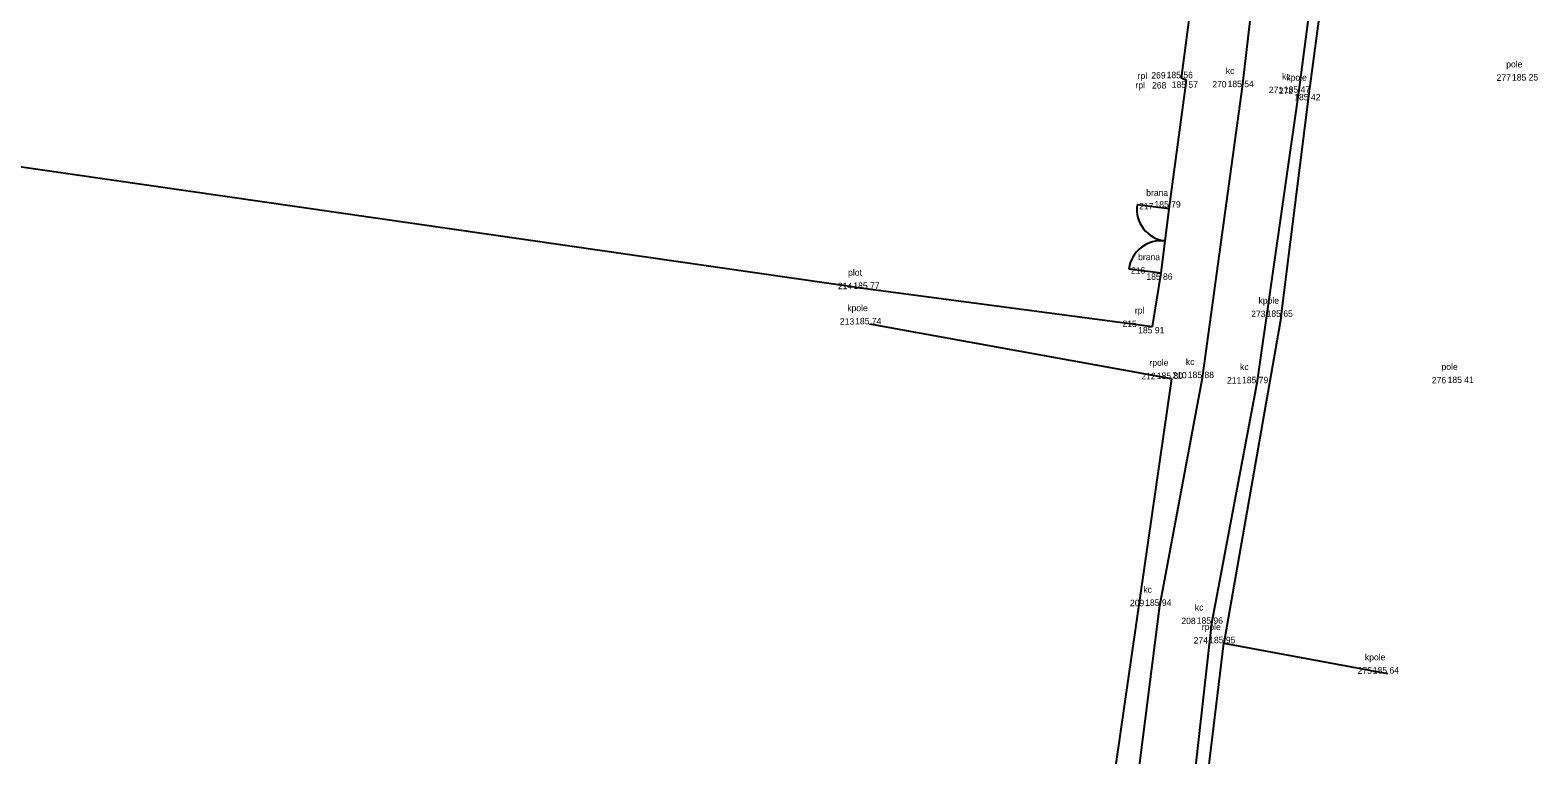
# Model space of a CAD drawing. Extents: x -598527 to -598215, y -1172822 to -1172560.
# Drawn here: x -598316.7 to -598246.1, y -1172679.2 to -1172645.3 of the extents above; entities that cross this region are included whole.
import ezdxf

# ---------------------------------------------------------------- set-up
doc = ezdxf.new("R2010")
doc.units = 0
for name, color, linetype in [('Body', 7, 'Continuous'), ('Body čísla', 7, 'Continuous'), ('Kody', 7, 'Continuous'), ('Kraj pole', 7, 'Continuous'), ('PATTERN_CLASS', 7, 'Continuous'), ('Ploty', 7, 'Continuous'), ('Výšky', 7, 'Continuous')]:
    doc.layers.add(name, color=color, linetype=linetype)

msp = doc.modelspace()

# ---------------------------------------------------------------- linework, layer by layer
at = {"layer": 'Body'}
for p, q in [((-598262.77, -1172647.51), (-598262.77, -1172647.51)), ((-598262.53, -1172647.63), (-598262.53, -1172647.63)), ((-598259.91, -1172647.93), (-598259.91, -1172647.93)), ((-598246.6, -1172647.62), (-598246.6, -1172647.62)), ((-598257.28, -1172648.19), (-598257.28, -1172648.19)), ((-598256.79, -1172648.24), (-598256.79, -1172648.24)), ((-598263.34, -1172653.64), (-598263.34, -1172653.64)), ((-598263.72, -1172656.65), (-598263.72, -1172656.65)), ((-598277.44, -1172657.38), (-598277.44, -1172657.38)), ((-598277.35, -1172659.04), (-598277.35, -1172659.04)), ((-598264.12, -1172659.15), (-598264.12, -1172659.15)), ((-598258.09, -1172658.69), (-598258.09, -1172658.69)), ((-598263.23, -1172661.6), (-598263.23, -1172661.6)), ((-598261.78, -1172661.56), (-598261.78, -1172661.56)), ((-598259.24, -1172661.8), (-598259.24, -1172661.8)), ((-598249.63, -1172661.79), (-598249.63, -1172661.79)), ((-598263.77, -1172672.23), (-598263.77, -1172672.23)), ((-598261.36, -1172673.07), (-598261.36, -1172673.07)), ((-598260.78, -1172673.98), (-598260.78, -1172673.98)), ((-598253.11, -1172675.4), (-598253.11, -1172675.4))]:
    msp.add_line(p, q, dxfattribs=at)
at = {"layer": 'Kraj pole'}
for p, q in [((-598256.79, -1172648.24), (-598255.25, -1172636.64)), ((-598258.09, -1172658.69), (-598256.79, -1172648.24)), ((-598263.23, -1172661.6), (-598277.35, -1172659.04)), ((-598258.09, -1172658.69), (-598260.78, -1172673.98)), ((-598263.23, -1172661.6), (-598266.75, -1172685.88)), ((-598266.91, -1172724.44), (-598260.78, -1172673.98)), ((-598260.78, -1172673.98), (-598253.11, -1172675.4))]:
    msp.add_line(p, q, dxfattribs=at)
at = {"layer": 'PATTERN_CLASS'}
for points in [[(-598268.17, -1172706.75), (-598265.5, -1172685.75), (-598263.77, -1172672.23), (-598261.78, -1172661.56), (-598259.91, -1172647.93), (-598258.56, -1172636.35), (-598257.55, -1172628.24), (-598255.85, -1172620.63), (-598252.54, -1172611.06), (-598250.18, -1172605.62), (-598248.3, -1172599.38), (-598247.28, -1172594.11), (-598247.12, -1172592.75), (-598247.32, -1172591.46), (-598247.682, -1172590.57), (-598248.25, -1172589.72), (-598249.298, -1172588.918), (-598249.871, -1172588.59), (-598250.6, -1172588.3), (-598252.47, -1172587.89)], [(-598253.34, -1172621.16), (-598254.92, -1172628.91), (-598255.77, -1172636.64), (-598257.28, -1172648.19), (-598259.24, -1172661.8), (-598261.36, -1172673.07), (-598262.76, -1172685.61)]]:
    msp.add_lwpolyline(points, dxfattribs=at)
at = {"layer": 'Ploty'}
for p, q in [((-598262.77, -1172647.51), (-598262.28, -1172643.81)), ((-598346.69, -1172647.4), (-598277.44, -1172657.38)), ((-598263.34, -1172653.64), (-598262.53, -1172647.63)), ((-598262.53, -1172647.63), (-598262.77, -1172647.51)), ((-598263.34, -1172653.64), (-598264.845, -1172653.45)), ((-598263.72, -1172656.65), (-598263.34, -1172653.64)), ((-598263.72, -1172656.65), (-598265.225, -1172656.46)), ((-598264.12, -1172659.15), (-598263.72, -1172656.65)), ((-598277.44, -1172657.38), (-598264.12, -1172659.15))]:
    msp.add_line(p, q, dxfattribs=at)
for centre, start, end in [((-598263.34, -1172653.64), 172.80471, 262.80471), ((-598263.72, -1172656.65), 82.80471, 172.80471)]:
    msp.add_arc(centre, 1.517, start, end, dxfattribs=at)

# ---------------------------------------------------------------- texts
at = {"layer": 'Body čísla'}
for s, p in [('269', (-598264.176, -1172647.533)), ('268', (-598264.142, -1172648.002)), ('270', (-598261.32, -1172647.953)), ('271', (-598258.671, -1172648.213)), ('272', (-598258.201, -1172648.263)), ('277', (-598248.008, -1172647.643)), ('217', (-598264.748, -1172653.663)), ('216', (-598265.127, -1172656.673)), ('214', (-598278.854, -1172657.403)), ('273', (-598259.497, -1172658.713)), ('213', (-598278.757, -1172659.063)), ('215', (-598265.525, -1172659.173)), ('212', (-598264.641, -1172661.623)), ('210', (-598263.19, -1172661.583)), ('211', (-598260.631, -1172661.823)), ('276', (-598251.037, -1172661.813)), ('209', (-598265.176, -1172672.253)), ('208', (-598262.768, -1172673.093)), ('274', (-598262.194, -1172674.003)), ('275', (-598254.515, -1172675.423))]:
    msp.add_text(s, height=0.3, dxfattribs=at).set_placement(p)
at = {"layer": 'Kody'}
for s, p in [('rpl', (-598264.816, -1172647.557)), ('kc', (-598260.688, -1172647.323)), ('kc', (-598258.058, -1172647.583)), ('pole', (-598247.557, -1172647.013)), ('rpl', (-598264.919, -1172647.995)), ('kpole', (-598257.854, -1172647.633)), ('brana', (-598264.415, -1172653.033)), ('brana', (-598264.795, -1172656.043)), ('plot', (-598278.375, -1172656.773)), ('kpole', (-598259.154, -1172658.083)), ('kpole', (-598278.414, -1172658.433)), ('rpl', (-598264.946, -1172658.543)), ('rpole', (-598264.263, -1172660.993)), ('kc', (-598262.558, -1172660.953)), ('kc', (-598260.018, -1172661.193)), ('pole', (-598250.587, -1172661.183)), ('kc', (-598264.548, -1172671.623)), ('kc', (-598262.138, -1172672.463)), ('rpole', (-598261.813, -1172673.373)), ('kpole', (-598254.174, -1172674.793))]:
    msp.add_text(s, height=0.3, dxfattribs=at).set_placement(p)
at = {"layer": 'Výšky'}
for s, p in [('185 56', (-598263.458, -1172647.518)), ('185 57', (-598263.219, -1172647.969)), ('185 54', (-598260.604, -1172647.938)), ('185 47', (-598257.969, -1172648.198)), ('185 25', (-598247.286, -1172647.628)), ('185 42', (-598257.481, -1172648.556)), ('185 79', (-598264.027, -1172653.578)), ('185 77', (-598278.129, -1172657.388)), ('185 86', (-598264.408, -1172656.965)), ('185 65', (-598258.776, -1172658.698)), ('185 74', (-598278.044, -1172659.048)), ('185 91', (-598264.791, -1172659.472)), ('185 80', (-598263.92, -1172661.608)), ('185 88', (-598262.468, -1172661.568)), ('185 79', (-598259.927, -1172661.808)), ('185 41', (-598250.301, -1172661.798)), ('185 94', (-598264.464, -1172672.238)), ('185 96', (-598262.048, -1172673.078)), ('185 95', (-598261.466, -1172673.988)), ('185 64', (-598253.804, -1172675.408))]:
    msp.add_text(s, height=0.3, dxfattribs=at).set_placement(p)

doc.saveas('drawing.dxf')
